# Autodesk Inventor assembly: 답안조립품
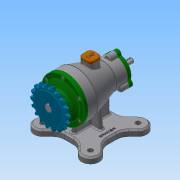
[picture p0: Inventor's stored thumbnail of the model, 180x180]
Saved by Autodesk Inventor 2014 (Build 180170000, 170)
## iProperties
Created: 2018-03
Part Number: 답안조립품
Document SubType Name: Assembly
Designer: 601-11
Author: 601-11
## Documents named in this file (15)
- C:\Users\601-11\Desktop\480308V1012\답안조립품.iam
- C:\Users\601-11\Desktop\480308V1012\본체.ipt
- C:\Users\601-11\Desktop\480308V1012\뒤커버.ipt
- C:\Users\601-11\Desktop\480308V1012\앞커버.ipt
- C:\Users\601-11\Desktop\480308V1012\베어링-6200.ipt
- C:\Users\601-11\Desktop\480308V1012\베어링-6203.ipt
- C:\Users\601-11\Desktop\480308V1012\축.ipt
- C:\Users\601-11\Desktop\480308V1012\키 5 x 5.ipt
- 키 5 x 5.ipt
- C:\Users\601-11\Desktop\480308V1012\볼트 M4 x 12.ipt
- 볼트 M4 x 12.ipt
- C:\Users\601-11\Desktop\480308V1012\오일 실 17 30 8.ipt
- C:\Users\601-11\Desktop\480308V1012\오일 실 10 20 7.ipt
- C:\Users\601-11\Desktop\480308V1012\마개.ipt
- C:\Users\601-11\Desktop\480308V1012\스프로킷.ipt
